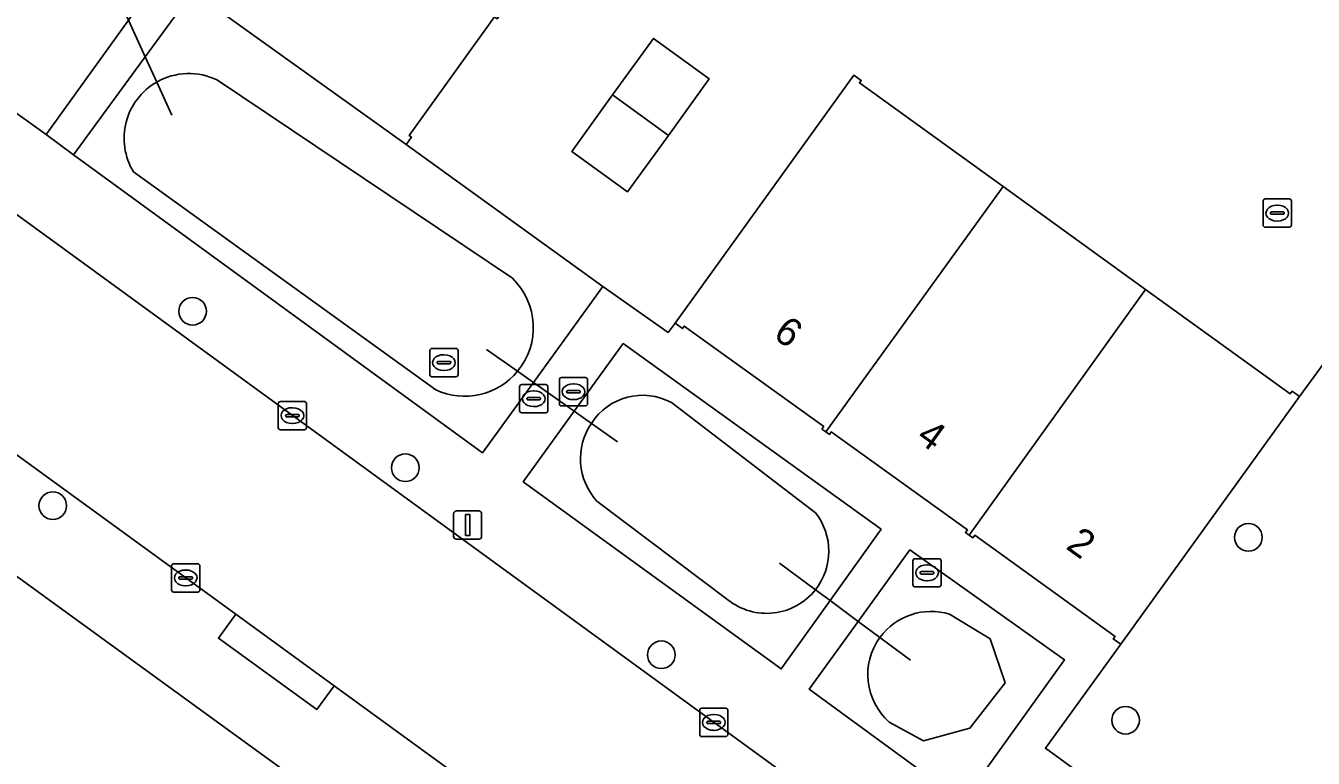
# Model space of a CAD drawing. Extents: x 159674 to 160531, y 382172 to 382904.
# Drawn here: x 160023.5 to 160069.09, y 382438.2 to 382464.14 of the extents above; entities that cross this region are included whole.
import ezdxf

# ---------------------------------------------------------------- set-up
doc = ezdxf.new("R2010")
doc.units = 0
for name, color, linetype in [('IMGEO_Boom', 7, 'Continuous'), ('IMGEO_Duiker', 7, 'Continuous'), ('IMGEO_Erf', 7, 'Continuous'), ('IMGEO_Groenvoorziening', 7, 'Continuous'), ('IMGEO_Kolk', 7, 'Continuous'), ('IMGEO_Lichtmast', 7, 'Continuous'), ('IMGEO_Pand', 7, 'Continuous'), ('IMGEO_Pand_nummerreeks', 7, 'Continuous'), ('IMGEO_Rijbaan_lokaal_open', 7, 'Continuous'), ('IMGEO_Rioolput', 7, 'Continuous'), ('IMGEO_Voetpad_open', 7, 'Continuous'), ('IMGEO_Waterloop', 7, 'Continuous')]:
    doc.layers.add(name, color=color, linetype=linetype)

msp = doc.modelspace()

# ---------------------------------------------------------------- linework, layer by layer
at = {"layer": 'IMGEO_Boom'}
for centre in [(160029.407, 382454.029), (160036.941, 382448.488), (160024.457, 382447.144), (160066.793, 382446.022), (160046.006, 382441.864), (160062.444, 382439.547)]:
    msp.add_circle(centre, 0.489, dxfattribs=at)
at = {"layer": 'IMGEO_Duiker'}
for points in [[(160028.671, 382460.968), (160028.136, 382462.142), (160027.725, 382463.041), (160027.135, 382464.334), (160026.399, 382465.948), (160025.818, 382467.221)], [(160044.452, 382449.408), (160043.529, 382450.059), (160042.922, 382450.487), (160041.474, 382451.508), (160040.915, 382451.903), (160039.813, 382452.68)], [(160054.834, 382441.676), (160053.747, 382442.479), (160052.977, 382443.048), (160051.982, 382443.784), (160051.461, 382444.169), (160050.195, 382445.105)]]:
    msp.add_lwpolyline(points, dxfattribs=at)
at = {"layer": 'IMGEO_Erf'}
for points in [[(160095.853, 382488.776), (160093.109, 382485.042), (160086.78, 382476.254), (160084.42, 382472.917), (160083.291, 382471.347), (160082.163, 382469.777), (160081.035, 382468.207), (160079.906, 382466.638), (160078.778, 382465.068), (160077.649, 382463.498), (160076.521, 382461.928), (160075.392, 382460.359), (160074.264, 382458.789), (160073.136, 382457.219), (160072.007, 382455.649), (160068.6, 382451.01), (160062.271, 382442.237), (160059.604, 382438.555), (160125.462, 382390.566)], [(160040.103, 382464.454), (160037.071, 382460.254), (160037.16, 382460.189), (160036.972, 382459.928), (160043.937, 382454.91), (160046.246, 382453.281), (160046.492, 382453.604), (160052.826, 382462.394), (160053.085, 382462.205), (160053.022, 382462.117), (160058.111, 382458.444), (160063.155, 382454.804), (160068.274, 382451.11), (160068.338, 382451.199), (160068.6, 382451.01), (160072.007, 382455.649)], [(160020.603, 382421.017), (160015.871, 382424.569), (160017.315, 382426.492), (160018.807, 382428.481), (160023.542, 382424.928), (160028.125, 382430.798), (160023.1, 382434.457), (160024.594, 382436.509), (160029.619, 382432.851), (160033.01, 382437.511), (160011.345, 382453.23)]]:
    msp.add_lwpolyline(points, dxfattribs=at)
msp.add_lwpolyline([(160046.256, 382460.258), (160044.807, 382458.257), (160042.831, 382459.689), (160044.28, 382461.69), (160045.728, 382463.69), (160047.704, 382462.258)], close=True, dxfattribs=at)
at = {"layer": 'IMGEO_Groenvoorziening'}
for points in [[(160037.642, 382478.923), (160031.503, 382483.33), (160023.13, 382471.823), (160022.611, 382472.173), (160019.765, 382468.28), (160020.141, 382468.006), (160019.056, 382466.519), (160018.758, 382466.11), (160019.353, 382463.773), (160024.222, 382460.289), (160027.135, 382464.334)], [(160036.972, 382459.928), (160029.413, 382465.356), (160027.725, 382463.041), (160025.191, 382459.567), (160039.671, 382449.018), (160041.474, 382451.508), (160043.937, 382454.91)], [(160044.658, 382452.884), (160042.922, 382450.487), (160041.115, 382447.994), (160050.253, 382441.367), (160051.982, 382443.784), (160053.788, 382446.31)], [(160054.806, 382445.584), (160052.977, 382443.048), (160051.245, 382440.646), (160056.683, 382436.674), (160058.575, 382439.306), (160060.282, 382441.681)]]:
    msp.add_lwpolyline(points, close=True, dxfattribs=at)
for points in [[(160030.284, 382462.211), (160040.732, 382455.196)], [(160038.018, 382451.248), (160027.312, 382458.967)], [(160046.37, 382450.793), (160051.466, 382446.887)], [(160048.362, 382443.814), (160043.723, 382447.303)], [(160056.213, 382443.302), (160057.65, 382442.427), (160058.184, 382440.877)], [(160058.184, 382440.877), (160056.933, 382439.263), (160055.284, 382438.815), (160054.078, 382439.477)]]:
    msp.add_lwpolyline(points, dxfattribs=at)
for centre, radius, start, end in [((160029.275, 382460.154), 2.291, 63.8665, 119.8132), ((160029.276, 382460.152), 2.294, 119.8003, 211.102), ((160039.043, 382453.451), 2.429, 320.4275, 45.9341), ((160039.043, 382453.446), 2.426, 244.9923, 320.488), ((160045.345, 382448.896), 2.156, 61.6085, 147.3638), ((160045.369, 382448.804), 2.227, 145.6896, 222.3634), ((160049.745, 382445.531), 2.191, 321.5638, 38.2254), ((160049.735, 382445.528), 2.197, 231.2991, 321.7707), ((160055.558, 382441.16), 2.24, 72.9883, 143.9234), ((160055.557, 382441.159), 2.24, 143.9067, 228.6773)]:
    msp.add_arc(centre, radius, start, end, dxfattribs=at)
at = {"layer": 'IMGEO_Kolk'}
for p, q in [((160037.807, 382451.784), (160037.807, 382452.636)), ((160037.882, 382452.71), (160038.734, 382452.71)), ((160038.295, 382452.49), (160038.32, 382452.49)), ((160038.808, 382452.636), (160038.808, 382451.784)), ((160038.066, 382452.204), (160038.066, 382452.216)), ((160038.504, 382452.167), (160038.106, 382452.167)), ((160038.109, 382452.253), (160038.507, 382452.253)), ((160038.318, 382451.93), (160038.293, 382451.93)), ((160038.55, 382452.216), (160038.55, 382452.204)), ((160038.734, 382451.71), (160037.882, 382451.71)), ((160032.443, 382449.907), (160032.443, 382450.759)), ((160032.518, 382450.833), (160033.37, 382450.833)), ((160032.931, 382450.613), (160032.956, 382450.613)), ((160033.444, 382450.759), (160033.444, 382449.907)), ((160032.702, 382450.327), (160032.702, 382450.339)), ((160033.14, 382450.29), (160032.742, 382450.29)), ((160032.745, 382450.376), (160033.143, 382450.376)), ((160032.954, 382450.053), (160032.929, 382450.053)), ((160033.186, 382450.339), (160033.186, 382450.327)), ((160033.37, 382449.833), (160032.518, 382449.833)), ((160028.663, 382444.161), (160028.663, 382445.013)), ((160028.738, 382445.087), (160029.59, 382445.087)), ((160029.664, 382445.013), (160029.664, 382444.161)), ((160028.922, 382444.581), (160028.922, 382444.593)), ((160029.36, 382444.544), (160028.962, 382444.544)), ((160028.965, 382444.63), (160029.363, 382444.63)), ((160029.151, 382444.867), (160029.176, 382444.867)), ((160029.406, 382444.593), (160029.406, 382444.581)), ((160029.59, 382444.087), (160028.738, 382444.087)), ((160029.174, 382444.307), (160029.149, 382444.307)), ((160047.438, 382439.969), (160048.29, 382439.969)), ((160047.363, 382439.043), (160047.363, 382439.895)), ((160047.665, 382439.512), (160048.063, 382439.512)), ((160047.851, 382439.749), (160047.876, 382439.749)), ((160048.364, 382439.895), (160048.364, 382439.043)), ((160047.622, 382439.463), (160047.622, 382439.475)), ((160048.06, 382439.426), (160047.662, 382439.426)), ((160047.874, 382439.189), (160047.849, 382439.189)), ((160048.106, 382439.475), (160048.106, 382439.463)), ((160048.29, 382438.969), (160047.438, 382438.969))]:
    msp.add_line(p, q, dxfattribs=at)
for points in [[(160037.807, 382451.784), (160037.807, 382452.636)], [(160037.882, 382452.71), (160038.734, 382452.71)], [(160038.808, 382452.636), (160038.808, 382451.784)], [(160038.734, 382451.71), (160037.882, 382451.71)], [(160032.443, 382449.907), (160032.443, 382450.759)], [(160032.518, 382450.833), (160033.37, 382450.833)], [(160033.444, 382450.759), (160033.444, 382449.907)], [(160033.37, 382449.833), (160032.518, 382449.833)], [(160028.663, 382444.161), (160028.663, 382445.013)], [(160028.738, 382445.087), (160029.59, 382445.087)], [(160029.664, 382445.013), (160029.664, 382444.161)], [(160029.59, 382444.087), (160028.738, 382444.087)], [(160047.438, 382439.969), (160048.29, 382439.969)], [(160047.363, 382439.043), (160047.363, 382439.895)], [(160048.364, 382439.895), (160048.364, 382439.043)], [(160048.29, 382438.969), (160047.438, 382438.969)]]:
    msp.add_lwpolyline(points, dxfattribs=at)
for centre, radius, start, end in [((160037.884, 382452.634), 0.0765, 91.552, 178.448), ((160037.884, 382452.634), 0.0765, 91.552, 178.448), ((160038.732, 382452.634), 0.0765, 1.552, 88.448), ((160038.732, 382452.634), 0.0765, 1.552, 88.448), ((160038.106, 382452.213), 0.0403, 85.8775, 175.7526), ((160038.103, 382452.203), 0.0366, 178.938, 274.7102), ((160038.507, 382452.21), 0.043, 264.8664, 352.4533), ((160038.511, 382452.215), 0.0386, 1.7309, 96.639), ((160037.884, 382451.786), 0.0765, 181.552, 268.448), ((160037.884, 382451.786), 0.0765, 181.552, 268.448), ((160038.732, 382451.786), 0.0765, 271.552, 358.448), ((160038.732, 382451.786), 0.0765, 271.552, 358.448), ((160032.52, 382450.757), 0.0765, 91.552, 178.448), ((160032.52, 382450.757), 0.0765, 91.552, 178.448), ((160033.368, 382450.757), 0.0765, 1.552, 88.448), ((160033.368, 382450.757), 0.0765, 1.552, 88.448), ((160032.742, 382450.336), 0.0403, 85.8775, 175.7526), ((160032.739, 382450.326), 0.0366, 178.938, 274.7102), ((160033.143, 382450.333), 0.043, 264.8664, 352.4533), ((160033.147, 382450.338), 0.0386, 1.7309, 96.639), ((160032.52, 382449.909), 0.0765, 181.552, 268.448), ((160032.52, 382449.909), 0.0765, 181.552, 268.448), ((160033.368, 382449.909), 0.0765, 271.552, 358.448), ((160033.368, 382449.909), 0.0765, 271.552, 358.448), ((160028.74, 382445.011), 0.0765, 91.552, 178.448), ((160028.74, 382445.011), 0.0765, 91.552, 178.448), ((160029.588, 382445.011), 0.0765, 1.552, 88.448), ((160029.588, 382445.011), 0.0765, 1.552, 88.448), ((160028.962, 382444.59), 0.0403, 85.8775, 175.7526), ((160028.959, 382444.58), 0.0366, 178.938, 274.7102), ((160029.363, 382444.587), 0.043, 264.8664, 352.4533), ((160029.367, 382444.592), 0.0386, 1.7309, 96.639), ((160028.74, 382444.163), 0.0765, 181.552, 268.448), ((160028.74, 382444.163), 0.0765, 181.552, 268.448), ((160029.588, 382444.163), 0.0765, 271.552, 358.448), ((160029.588, 382444.163), 0.0765, 271.552, 358.448), ((160047.44, 382439.893), 0.0765, 91.552, 178.448), ((160047.44, 382439.893), 0.0765, 91.552, 178.448), ((160048.288, 382439.893), 0.0765, 1.552, 88.448), ((160048.288, 382439.893), 0.0765, 1.552, 88.448), ((160047.662, 382439.472), 0.0403, 85.8775, 175.7526), ((160048.067, 382439.474), 0.0386, 1.7309, 96.639), ((160047.44, 382439.045), 0.0765, 181.552, 268.448), ((160047.44, 382439.045), 0.0765, 181.552, 268.448), ((160047.659, 382439.462), 0.0366, 178.938, 274.7102), ((160048.063, 382439.469), 0.043, 264.8664, 352.4533), ((160048.288, 382439.045), 0.0765, 271.552, 358.448), ((160048.288, 382439.045), 0.0765, 271.552, 358.448)]:
    msp.add_arc(centre, radius, start, end, dxfattribs=at)
for centre, major_axis, ratio, start_param, end_param in [((160038.294, 382452.21), (-0.387, 0.002), 0.722429, 4.712389, 7.853982), ((160038.319, 382452.21), (-0.39, 0.002), 0.717154, 1.570796, 4.712389), ((160032.93, 382450.333), (-0.387, 0.002), 0.722429, 4.712389, 7.853982), ((160032.955, 382450.333), (-0.39, 0.002), 0.717154, 1.570796, 4.712389), ((160029.15, 382444.587), (-0.387, 0.002), 0.722429, 4.712389, 7.853982), ((160029.175, 382444.587), (-0.39, 0.002), 0.717154, 1.570796, 4.712389), ((160047.85, 382439.469), (-0.387, 0.002), 0.722429, 4.712389, 7.853982), ((160047.875, 382439.469), (-0.39, 0.002), 0.717154, 1.570796, 4.712389)]:
    msp.add_ellipse(centre, major_axis=major_axis, ratio=ratio, start_param=start_param, end_param=end_param, dxfattribs=at)
at = {"layer": 'IMGEO_Lichtmast'}
for p, q in [((160038.652, 382446.058), (160038.652, 382446.858)), ((160038.652, 382446.858), (160038.652, 382446.058)), ((160038.752, 382446.958), (160039.542, 382446.958)), ((160039.542, 382446.958), (160038.752, 382446.958)), ((160039.642, 382446.858), (160039.642, 382446.058)), ((160039.642, 382446.058), (160039.642, 382446.858)), ((160039.542, 382445.958), (160038.752, 382445.958)), ((160038.752, 382445.958), (160039.542, 382445.958))]:
    msp.add_line(p, q, dxfattribs=at)
msp.add_lwpolyline([(160039.072, 382446.833), (160039.222, 382446.833), (160039.222, 382446.083), (160039.072, 382446.083), (160039.072, 382446.833)], dxfattribs=at)
for centre, start, end in [((160038.752, 382446.858), 90, 180), ((160038.752, 382446.858), 90, 180), ((160039.542, 382446.858), 0, 90), ((160039.542, 382446.858), 360, 90), ((160038.752, 382446.058), 180, 270), ((160038.752, 382446.058), 180, 270), ((160039.542, 382446.058), 270, 0), ((160039.542, 382446.058), 270, 0)]:
    msp.add_arc(centre, 0.1, start, end, dxfattribs=at)
at = {"layer": 'IMGEO_Pand'}
for points in [[(160032.597, 382470.065), (160032.503, 382469.934), (160032.593, 382469.87), (160029.557, 382465.648), (160029.467, 382465.712), (160029.28, 382465.451), (160029.413, 382465.356), (160036.972, 382459.928), (160037.16, 382460.189), (160037.071, 382460.254), (160040.103, 382464.454), (160040.193, 382464.389), (160040.276, 382464.504)], [(160045.728, 382463.69), (160044.28, 382461.69), (160046.256, 382460.258), (160047.704, 382462.258)], [(160058.111, 382458.444), (160053.022, 382462.117), (160053.085, 382462.205), (160052.826, 382462.394), (160046.492, 382453.604), (160046.754, 382453.415), (160046.818, 382453.504), (160051.758, 382449.946), (160051.694, 382449.857), (160051.825, 382449.763)], [(160046.256, 382460.258), (160044.28, 382461.69), (160042.831, 382459.689), (160044.807, 382458.257)], [(160063.155, 382454.804), (160058.111, 382458.444), (160051.825, 382449.763), (160051.955, 382449.668), (160052.02, 382449.758), (160056.843, 382446.284), (160056.778, 382446.194), (160056.909, 382446.1)], [(160068.6, 382451.01), (160068.338, 382451.199), (160068.274, 382451.11), (160063.155, 382454.804), (160056.909, 382446.1), (160057.04, 382446.006), (160057.105, 382446.095), (160062.074, 382442.515), (160062.009, 382442.426), (160062.271, 382442.237)]]:
    msp.add_lwpolyline(points, close=True, dxfattribs=at)
at = {"layer": 'IMGEO_Rijbaan_lokaal_open'}
for points in [[(160123.455, 382384.426), (160018.366, 382460.946)], [(160014.616, 382455.167), (160030.935, 382443.3), (160034.415, 382440.769), (160099.29, 382393.592), (160102.339, 382391.375), (160119.102, 382379.184)]]:
    msp.add_lwpolyline(points, dxfattribs=at)
at = {"layer": 'IMGEO_Rioolput'}
for p, q in [((160067.315, 382457.078), (160067.315, 382457.93)), ((160067.39, 382458.004), (160068.242, 382458.004)), ((160067.803, 382457.784), (160067.828, 382457.784)), ((160068.316, 382457.93), (160068.316, 382457.078)), ((160067.574, 382457.498), (160067.574, 382457.51)), ((160068.012, 382457.461), (160067.614, 382457.461)), ((160067.617, 382457.547), (160068.015, 382457.547)), ((160068.058, 382457.51), (160068.058, 382457.498)), ((160068.242, 382457.004), (160067.39, 382457.004)), ((160067.826, 382457.224), (160067.801, 382457.224)), ((160040.988, 382450.506), (160040.988, 382451.358)), ((160041.063, 382451.432), (160041.915, 382451.432)), ((160041.989, 382451.358), (160041.989, 382450.506)), ((160042.394, 382450.753), (160042.394, 382451.605)), ((160042.469, 382451.679), (160043.321, 382451.679)), ((160042.882, 382451.459), (160042.907, 382451.459)), ((160043.395, 382451.605), (160043.395, 382450.753)), ((160041.247, 382450.926), (160041.247, 382450.938)), ((160041.29, 382450.975), (160041.688, 382450.975)), ((160041.476, 382451.212), (160041.501, 382451.212)), ((160041.731, 382450.938), (160041.731, 382450.926)), ((160042.653, 382451.173), (160042.653, 382451.185)), ((160043.091, 382451.136), (160042.693, 382451.136)), ((160042.696, 382451.222), (160043.094, 382451.222)), ((160042.905, 382450.899), (160042.88, 382450.899)), ((160043.137, 382451.185), (160043.137, 382451.173)), ((160041.685, 382450.889), (160041.287, 382450.889)), ((160041.499, 382450.652), (160041.474, 382450.652)), ((160043.321, 382450.679), (160042.469, 382450.679)), ((160041.915, 382450.432), (160041.063, 382450.432)), ((160054.913, 382444.341), (160054.913, 382445.193)), ((160054.988, 382445.267), (160055.84, 382445.267)), ((160055.401, 382445.047), (160055.426, 382445.047)), ((160055.914, 382445.193), (160055.914, 382444.341)), ((160055.172, 382444.761), (160055.172, 382444.773)), ((160055.61, 382444.724), (160055.212, 382444.724)), ((160055.215, 382444.81), (160055.613, 382444.81)), ((160055.656, 382444.773), (160055.656, 382444.761)), ((160055.84, 382444.267), (160054.988, 382444.267)), ((160055.424, 382444.487), (160055.399, 382444.487))]:
    msp.add_line(p, q, dxfattribs=at)
for points in [[(160067.315, 382457.078), (160067.315, 382457.93)], [(160067.39, 382458.004), (160068.242, 382458.004)], [(160068.316, 382457.93), (160068.316, 382457.078)], [(160068.242, 382457.004), (160067.39, 382457.004)], [(160040.988, 382450.506), (160040.988, 382451.358)], [(160041.063, 382451.432), (160041.915, 382451.432)], [(160041.989, 382451.358), (160041.989, 382450.506)], [(160042.394, 382450.753), (160042.394, 382451.605)], [(160042.469, 382451.679), (160043.321, 382451.679)], [(160043.395, 382451.605), (160043.395, 382450.753)], [(160043.321, 382450.679), (160042.469, 382450.679)], [(160041.915, 382450.432), (160041.063, 382450.432)], [(160054.913, 382444.341), (160054.913, 382445.193)], [(160054.988, 382445.267), (160055.84, 382445.267)], [(160055.914, 382445.193), (160055.914, 382444.341)], [(160055.84, 382444.267), (160054.988, 382444.267)]]:
    msp.add_lwpolyline(points, dxfattribs=at)
for centre, radius, start, end in [((160067.392, 382457.928), 0.0765, 91.552, 178.448), ((160067.392, 382457.928), 0.0765, 91.552, 178.448), ((160068.24, 382457.928), 0.0765, 1.552, 88.448), ((160068.24, 382457.928), 0.0765, 1.552, 88.448), ((160067.614, 382457.507), 0.0403, 85.8775, 175.7526), ((160067.611, 382457.497), 0.0366, 178.938, 274.7102), ((160068.015, 382457.504), 0.043, 264.8664, 352.4533), ((160068.019, 382457.509), 0.0386, 1.7309, 96.639), ((160067.392, 382457.08), 0.0765, 181.552, 268.448), ((160067.392, 382457.08), 0.0765, 181.552, 268.448), ((160068.24, 382457.08), 0.0765, 271.552, 358.448), ((160068.24, 382457.08), 0.0765, 271.552, 358.448), ((160041.065, 382451.356), 0.0765, 91.552, 178.448), ((160041.065, 382451.356), 0.0765, 91.552, 178.448), ((160041.913, 382451.356), 0.0765, 1.552, 88.448), ((160041.913, 382451.356), 0.0765, 1.552, 88.448), ((160042.471, 382451.603), 0.0765, 91.552, 178.448), ((160042.471, 382451.603), 0.0765, 91.552, 178.448), ((160043.319, 382451.603), 0.0765, 1.552, 88.448), ((160043.319, 382451.603), 0.0765, 1.552, 88.448), ((160041.287, 382450.935), 0.0403, 85.8775, 175.7526), ((160041.284, 382450.925), 0.0366, 178.938, 274.7102), ((160041.688, 382450.932), 0.043, 264.8664, 352.4533), ((160041.692, 382450.937), 0.0386, 1.7309, 96.639), ((160042.693, 382451.182), 0.0403, 85.8775, 175.7526), ((160042.69, 382451.172), 0.0366, 178.938, 274.7102), ((160043.094, 382451.179), 0.043, 264.8664, 352.4533), ((160043.098, 382451.184), 0.0386, 1.7309, 96.639), ((160041.065, 382450.508), 0.0765, 181.552, 268.448), ((160041.065, 382450.508), 0.0765, 181.552, 268.448), ((160041.913, 382450.508), 0.0765, 271.552, 358.448), ((160041.913, 382450.508), 0.0765, 271.552, 358.448), ((160042.471, 382450.755), 0.0765, 181.552, 268.448), ((160042.471, 382450.755), 0.0765, 181.552, 268.448), ((160043.319, 382450.755), 0.0765, 271.552, 358.448), ((160043.319, 382450.755), 0.0765, 271.552, 358.448), ((160054.99, 382445.191), 0.0765, 91.552, 178.448), ((160054.99, 382445.191), 0.0765, 91.552, 178.448), ((160055.838, 382445.191), 0.0765, 1.552, 88.448), ((160055.838, 382445.191), 0.0765, 1.552, 88.448), ((160055.212, 382444.77), 0.0403, 85.8775, 175.7526), ((160055.209, 382444.76), 0.0366, 178.938, 274.7102), ((160055.613, 382444.767), 0.043, 264.8664, 352.4533), ((160055.617, 382444.772), 0.0386, 1.7309, 96.639), ((160054.99, 382444.343), 0.0765, 181.552, 268.448), ((160054.99, 382444.343), 0.0765, 181.552, 268.448), ((160055.838, 382444.343), 0.0765, 271.552, 358.448), ((160055.838, 382444.343), 0.0765, 271.552, 358.448)]:
    msp.add_arc(centre, radius, start, end, dxfattribs=at)
for centre, major_axis, ratio, start_param, end_param in [((160067.802, 382457.504), (-0.387, 0.002), 0.722429, 4.712389, 7.853982), ((160067.827, 382457.504), (-0.39, 0.002), 0.717154, 1.570796, 4.712389), ((160042.881, 382451.179), (-0.387, 0.002), 0.722429, 4.712389, 7.853982), ((160042.906, 382451.179), (-0.39, 0.002), 0.717154, 1.570796, 4.712389), ((160041.475, 382450.932), (-0.387, 0.002), 0.722429, 4.712389, 7.853982), ((160041.5, 382450.932), (-0.39, 0.002), 0.717154, 1.570796, 4.712389), ((160055.4, 382444.767), (-0.387, 0.002), 0.722429, 4.712389, 7.853982), ((160055.425, 382444.767), (-0.39, 0.002), 0.717154, 1.570796, 4.712389)]:
    msp.add_ellipse(centre, major_axis=major_axis, ratio=ratio, start_param=start_param, end_param=end_param, dxfattribs=at)
at = {"layer": 'IMGEO_Voetpad_open'}
for points in [[(160027.135, 382464.334), (160024.222, 382460.289), (160025.191, 382459.567), (160027.725, 382463.041), (160029.413, 382465.356)], [(160062.271, 382442.237), (160062.009, 382442.426), (160062.074, 382442.515), (160057.105, 382446.095), (160057.04, 382446.006), (160056.909, 382446.1), (160056.778, 382446.194), (160056.843, 382446.284), (160052.02, 382449.758), (160051.955, 382449.668), (160051.825, 382449.763), (160051.694, 382449.857), (160051.758, 382449.946), (160046.818, 382453.504), (160046.754, 382453.415), (160046.492, 382453.604), (160046.246, 382453.281), (160043.937, 382454.91), (160041.474, 382451.508), (160039.671, 382449.018), (160025.191, 382459.567), (160024.222, 382460.289), (160019.353, 382463.773)], [(160018.366, 382460.946), (160123.455, 382384.426), (160127.601, 382390.967)], [(160034.415, 382440.769), (160033.804, 382439.927), (160030.324, 382442.458), (160030.935, 382443.3), (160014.616, 382455.167)], [(160011.345, 382453.23), (160033.01, 382437.511), (160034.251, 382436.61), (160034.768, 382437.312), (160083.531, 382401.81), (160085.455, 382400.41), (160110.564, 382382.129), (160106.732, 382376.818), (160104.611, 382373.905), (160105.953, 382372.892), (160111.288, 382369.019), (160119.102, 382379.184), (160102.339, 382391.375), (160102.045, 382390.971), (160098.996, 382393.188), (160099.29, 382393.592), (160034.415, 382440.769)], [(160125.462, 382390.566), (160059.604, 382438.555), (160062.271, 382442.237)]]:
    msp.add_lwpolyline(points, dxfattribs=at)
for points in [[(160051.982, 382443.784), (160050.253, 382441.367), (160041.115, 382447.994), (160042.922, 382450.487), (160044.658, 382452.884), (160053.788, 382446.31)], [(160058.575, 382439.306), (160056.683, 382436.674), (160051.245, 382440.646), (160052.977, 382443.048), (160054.806, 382445.584), (160060.282, 382441.681)], [(160030.935, 382443.3), (160030.324, 382442.458), (160033.804, 382439.927), (160034.415, 382440.769)]]:
    msp.add_lwpolyline(points, close=True, dxfattribs=at)
at = {"layer": 'IMGEO_Waterloop'}
for points in [[(160040.732, 382455.196), (160030.284, 382462.211)], [(160027.312, 382458.967), (160038.018, 382451.248)], [(160051.466, 382446.887), (160046.37, 382450.793)], [(160043.723, 382447.303), (160048.362, 382443.814)], [(160058.184, 382440.877), (160057.65, 382442.427), (160056.213, 382443.302)], [(160054.078, 382439.477), (160055.284, 382438.815), (160056.933, 382439.263), (160058.184, 382440.877)]]:
    msp.add_lwpolyline(points, dxfattribs=at)
for centre, radius, start, end in [((160029.275, 382460.154), 2.291, 63.8665, 119.8132), ((160029.276, 382460.152), 2.294, 119.8003, 211.102), ((160039.043, 382453.451), 2.429, 320.4275, 45.9341), ((160039.043, 382453.446), 2.426, 244.9923, 320.488), ((160045.345, 382448.896), 2.156, 61.6085, 147.3638), ((160045.369, 382448.804), 2.227, 145.6896, 222.3634), ((160049.745, 382445.531), 2.191, 321.5638, 38.2254), ((160049.735, 382445.528), 2.197, 231.2991, 321.7707), ((160055.558, 382441.16), 2.24, 72.9883, 143.9234), ((160055.557, 382441.159), 2.24, 143.9067, 228.6773)]:
    msp.add_arc(centre, radius, start, end, dxfattribs=at)

# ---------------------------------------------------------------- texts
at = {"layer": 'IMGEO_Pand_nummerreeks'}
for s, rotation, p in [('6', 324.236, (160049.922, 382453.117)), ('4', 324.236, (160054.992, 382449.466)), ('2', 324.2302, (160060.292, 382445.647))]:
    msp.add_text(s, height=1, rotation=rotation, dxfattribs=at).set_placement(p)

doc.saveas('drawing.dxf')
